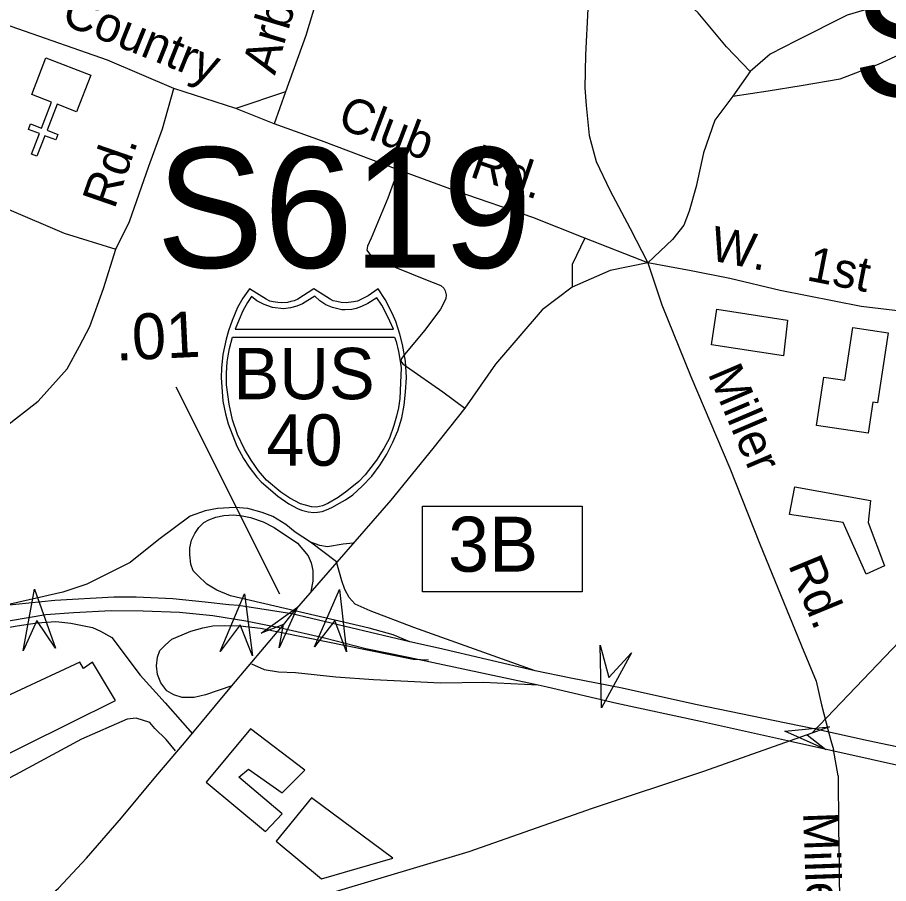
# Model space of a CAD drawing. Extents: x 1547597 to 1699558, y 810033 to 920809.
# Drawn here: x 1621385 to 1623759, y 854822 to 857184 of the extents above; entities that cross this region are included whole.
import ezdxf

# ---------------------------------------------------------------- set-up
doc = ezdxf.new("R2010")
doc.units = 0
for name, color, linetype in [('Exist Cultural Church CELL', 7, 'Continuous'), ('Exist Cultural Shopping Center Building Footprint', 7, 'Continuous'), ('Exist Cultural Warehouse Building Footprint', 7, 'Continuous'), ('Exist Railroad Mainline', 7, 'Continuous'), ('Exist Road Non-System Type 51', 7, 'Continuous'), ('Exist Road Non-System Type 51 Label', 7, 'Continuous'), ('Exist Road Primary Interstate Divided Center Attributed', 7, 'Continuous'), ('Exist Road Primary Interstate Interchange CELL', 7, 'Continuous'), ('Exist Road Primary Interstate Ramp 1 Lane Attributed', 7, 'Continuous'), ('Exist Road Primary Interstate Shield CELL', 7, 'Continuous'), ('Exist Road Primary Interstate Shield Number Label', 7, 'Continuous'), ('Exist Road Primary Interstate Structure Cantilever Sign Attributed CELL', 7, 'Continuous'), ('Exist Road Primary Interstate Structure Ovrhead Sign Attributed CELL', 7, 'Continuous'), ('Exist Road Primary Interstate Structure Ovrhead Sign Number Label', 7, 'Continuous'), ('Exist Road Primary US Mileage Hundredths English Label', 7, 'Continuous'), ('Exist Road Primary US UnDivided 4 Lane Attributed', 7, 'Continuous'), ('Exist Road Secondary Structure Standard Bridge Attributed CELL', 7, 'Continuous')]:
    doc.layers.add(name, color=color, linetype=linetype)

msp = doc.modelspace()

# ---------------------------------------------------------------- linework, layer by layer
at = {"layer": 'Exist Cultural Church CELL'}
msp.add_lwpolyline([(1621545.9, 856926.6), (1621492.8, 856947), (1621465.3, 856876), (1621495.2, 856864.5), (1621489.4, 856849.6), (1621459.6, 856861.1), (1621437.9, 856805), (1621423, 856810.8), (1621444.6, 856866.9), (1621414.8, 856878.4), (1621420.5, 856893.3), (1621450.4, 856881.8), (1621477.8, 856952.8), (1621424.1, 856973.7), (1621462.4, 857073), (1621584.3, 857025.9)], close=True, dxfattribs=at)
at = {"layer": 'Exist Cultural Shopping Center Building Footprint'}
msp.add_lwpolyline([(1620907.7, 854952.7), (1621651.9, 855321.6), (1621589.3, 855426), (1621564.9, 855408.6), (1621554.5, 855426), (1621137.2, 855231.1), (1621144.1, 855206.8), (1620883.3, 855081.5), (1620865.9, 855116.3), (1620834.6, 855098.9)], close=True, dxfattribs=at)
at = {"layer": 'Exist Cultural Warehouse Building Footprint'}
for points in [[(1623291.3, 856387.8), (1623484.1, 856357.9), (1623472.5, 856261.4), (1623276.3, 856291.3)], [(1623562.8, 856071.5), (1623583, 856203), (1623640, 856194.3), (1623662.2, 856338.6), (1623758.4, 856323.8), (1623729.1, 856133.1), (1623716.3, 856135.1), (1623703.2, 856049.9)], [(1623504.1, 855903.6), (1623710.3, 855867), (1623703.6, 855807.1), (1623748.5, 855688.9), (1623698.6, 855665.6), (1623635.4, 855807.1), (1623489.1, 855828.7)], [(1622020.2, 855244.5), (1621899, 855099), (1622060.6, 854964.2), (1622106.4, 855012.7), (1621987.9, 855112.4), (1622014.8, 855134), (1622106.4, 855069.3), (1622168.4, 855131.3)], [(1622213.5, 854835.4), (1622407.5, 854892), (1622186.6, 855056.5), (1622089.6, 854937.8)]]:
    msp.add_lwpolyline(points, close=True, dxfattribs=at)
at = {"layer": 'Exist Railroad Mainline'}
msp.add_lwpolyline([(1620826, 854318.2), (1621032.6, 854389.6), (1621343.6, 854489.6), (1621650.5, 854595.6), (1621961.6, 854699.6), (1622242.6, 854798.1), (1622615.9, 854910.1), (1622951.9, 855027.5), (1623255.9, 855128.9), (1623550.6, 855233.7), (1623868.5, 855565)], dxfattribs=at)
at = {"layer": 'Exist Road Non-System Type 51'}
for p, q in [((1623381.7, 857036.3), (1623334.7, 856969)), ((1621979.5, 856935.1), (1621810.7, 856989.7)), ((1622115.7, 856981.1), (1621979.5, 856935.1)), ((1622115.7, 856981.1), (1622084.7, 856893.3)), ((1622084.7, 856893.3), (1621979.5, 856935.1)), ((1623103.4, 856515), (1622930.9, 856581.8)), ((1623576.2, 855309.2), (1623595.4, 855236.4)), ((1623595.4, 855236.4), (1623601.9, 855212.1)), ((1623601.9, 855212.1), (1623608.7, 855187.8)), ((1623621.7, 855116.1), (1623608.7, 855187.8))]:
    msp.add_line(p, q, dxfattribs=at)
for points in [[(1622239.3, 857361), (1622213.2, 857275.9), (1622171.1, 857134.5), (1622115.7, 856981.1)], [(1622937.3, 857345.3), (1622939.2, 857207.3), (1622933, 857081.4), (1622931.6, 856991.6), (1622934.8, 856943.5), (1622943.3, 856861.5), (1622962.1, 856791.2), (1622999, 856712.7), (1623055.1, 856607.7), (1623103.4, 856515)], [(1623381.7, 857036.3), (1623317, 857103.2), (1623240.5, 857196.4), (1623158, 857271.7), (1623090.5, 857310.7), (1623009.2, 857338), (1622937.3, 857345.3)], [(1621810.7, 856989.7), (1621630, 857066.6), (1621385.8, 857152.6), (1621207, 857215.5), (1621073.8, 857259.6), (1620942.7, 857307.7)], [(1623956.4, 857232.7), (1623854.6, 857232.4), (1623748.4, 857220.1), (1623646, 857189.8), (1623507.1, 857120.2), (1623436.5, 857083.2), (1623381.7, 857036.3)], [(1623334.7, 856969), (1623430.9, 856983.4), (1623521, 856998), (1623627.2, 857016.3), (1623731.7, 857056.4), (1623812.3, 857093.2), (1623892.4, 857103.8), (1623968.3, 857100.6)], [(1621653.2, 856551.7), (1621690.3, 856627.1), (1621742.6, 856778.2), (1621780.1, 856879.7), (1621810.7, 856989.7)], [(1623334.7, 856969), (1623285.8, 856903.7), (1623254.4, 856814.3), (1623234.7, 856722.7), (1623215.7, 856655), (1623201.1, 856617.3), (1623170.5, 856577.9), (1623103.4, 856515)], [(1622422.4, 856768), (1622213.9, 856847.2), (1622084.7, 856893.3)], [(1622422.4, 856768), (1622394.6, 856690.5), (1622348.7, 856581.4), (1622338.7, 856559.6), (1622337.3, 856548.8), (1622346.6, 856535.6), (1622377.9, 856516.9), (1622497.1, 856469.1), (1622538.8, 856452.6), (1622546.7, 856445.5), (1622550.6, 856438.4), (1622553.5, 856427.3), (1622552.3, 856416.3), (1622537.9, 856388.6), (1622495, 856331.3), (1622444.1, 856270.1), (1622431.9, 856253.9), (1622429.8, 856246.3), (1622434.3, 856239.8), (1622445.5, 856232), (1622544.4, 856162.6), (1622603.8, 856118.2)], [(1622930.9, 856581.8), (1622789.9, 856638.1), (1622583.3, 856709.3), (1622422.4, 856768)], [(1621213.9, 856708.3), (1621361, 856660), (1621512, 856595.7), (1621653.2, 856551.7)], [(1622930.9, 856581.8), (1622897.2, 856509.8), (1622897.2, 856448)], [(1620678.7, 855654.7), (1620761, 855691.5), (1620912.2, 855775.2), (1621033.3, 855853.4), (1621154.2, 855927.6), (1621257.2, 856000), (1621350.2, 856066.5), (1621441, 856137.1), (1621520.3, 856226), (1621553.4, 856287.3), (1621582.1, 856341), (1621619.6, 856444.3), (1621653.2, 856551.7)], [(1623103.4, 856515), (1623000, 856493.3), (1622897.2, 856448)], [(1623948.2, 856365.4), (1623860.4, 856374.8), (1623684.9, 856395.6), (1623463.9, 856439.3), (1623326.6, 856471.5), (1623221, 856493), (1623103.4, 856515)], [(1623103.4, 856515), (1623141.5, 856399.6), (1623220.4, 856204.5), (1623326.6, 855955), (1623407.3, 855750), (1623482.9, 855566.3), (1623495.9, 855534.7), (1623522.2, 855470.2), (1623561.5, 855373.9), (1623576.2, 855309.2)], [(1622897.2, 856448), (1622815, 856386.3), (1622687.6, 856238.3), (1622603.8, 856118.2)], [(1622603.8, 856118.2), (1622517.3, 856008.2), (1622402.6, 855867.7), (1622132.4, 855557.4)], [(1621815.5, 855184.2), (1621789.8, 855214.7), (1621759.3, 855245.1), (1621745.3, 855261.5), (1621707.9, 855273.2), (1621683.8, 855270.1), (1621559, 855216), (1621379.8, 855118.6), (1621222.6, 855037.1), (1621106, 854978.9), (1621029.3, 854936)], [(1623621.7, 855116.1), (1623623, 854978.3), (1623624.1, 854864.3), (1623627, 854549.7)]]:
    msp.add_lwpolyline(points, dxfattribs=at)
at = {"layer": 'Exist Road Primary Interstate Divided Center Attributed'}
for points in [[(1622132.4, 855557.4), (1621987.3, 855580.3), (1621960.5, 855582.2), (1621896.7, 855589.9), (1621808.5, 855598.5), (1621707.9, 855603.2), (1621647.1, 855603.2), (1621486.4, 855593.6), (1621344.4, 855579.5)], [(1621094.5, 855465.5), (1621166.7, 855490.4), (1621252.9, 855513.8), (1621365.3, 855539.8), (1621462.3, 855555.5), (1621537.3, 855561.1), (1621639.9, 855567.2), (1621727.6, 855565.8), (1621826, 855561.8), (1621916.9, 855552.9), (1622007.3, 855538.9), (1622102.8, 855519.9)], [(1622796.2, 855402.7), (1622532.6, 855463.7), (1622454.4, 855481), (1622132.4, 855557.4)], [(1622102.8, 855519.9), (1622221.4, 855492.6), (1622334, 855462.8), (1622450.9, 855439.4), (1622804.5, 855363.8)], [(1623560, 855243.5), (1623480.4, 855259.4), (1623233.1, 855310.6), (1623032.6, 855354.7), (1622892.8, 855382), (1622796.2, 855402.7)], [(1622804.5, 855363.8), (1622829, 855358.6), (1623018.1, 855314), (1623246.3, 855265.4), (1623483.3, 855212.3)], [(1624233.7, 855069.8), (1623946.4, 855160.9), (1623703.8, 855211.6), (1623560, 855243.5)], [(1623483.3, 855212.3), (1623830.2, 855134.7), (1623968.5, 855100.4)]]:
    msp.add_lwpolyline(points, dxfattribs=at)
at = {"layer": 'Exist Road Primary Interstate Interchange CELL'}
msp.add_lwpolyline([(1622489.2, 855851), (1622924.1, 855851), (1622924.1, 855617.7), (1622489.2, 855617.7)], close=True, dxfattribs=at)
at = {"layer": 'Exist Road Primary Interstate Ramp 1 Lane Attributed'}
msp.add_line((1622254.6, 855699.5), (1622183.1, 855752.6), dxfattribs=at)
for points in [[(1622183.1, 855752.6), (1622141.3, 855780.4), (1622116, 855800.8), (1622080.4, 855822.8), (1622051.8, 855834.1), (1622012.9, 855844.4), (1621978.3, 855847.3), (1621930.3, 855844.6), (1621896.1, 855838.3), (1621855.7, 855824.3), (1621769.8, 855760.7), (1621691.6, 855697.6), (1621574, 855639), (1621508, 855616.5), (1621344.4, 855579.5)], [(1622454.4, 855481), (1622408.9, 855500.7), (1622343.3, 855518.9), (1621965.6, 855606.8), (1621928.1, 855622.3), (1621900.9, 855638.7), (1621876.6, 855662.6), (1621863.9, 855675.2), (1621856.9, 855693.5), (1621854.6, 855718.8), (1621854.6, 855738), (1621858.8, 855758.6), (1621868.6, 855777.1), (1621879.4, 855792.6), (1621892.5, 855806.7), (1621906.1, 855814.2), (1621925.3, 855821.2), (1621947.3, 855825.9), (1621974.5, 855827.3), (1621997.5, 855824.5), (1622020, 855820.7), (1622054.4, 855808.5), (1622084.4, 855792.8), (1622148.5, 855750), (1622177, 855715.7), (1622185.1, 855697.1), (1622189.9, 855675.8), (1622189.8, 855646.5), (1622184.2, 855618.7)], [(1622299.5, 855750.5), (1622272.3, 855748), (1622229.5, 855740.4), (1622208.5, 855744), (1622183.1, 855752.6)], [(1622796.2, 855402.7), (1622464.9, 855520.2), (1622346.3, 855565.8), (1622305, 855584.4), (1622289.3, 855602.2), (1622277.2, 855623.6), (1622268.7, 855647.9), (1622254.6, 855699.5)], [(1621094.5, 855465.5), (1621118.4, 855461.8), (1621178.4, 855478.2), (1621295.1, 855509.3), (1621384.1, 855524.8), (1621438.4, 855533.2), (1621489.5, 855536.5), (1621529.8, 855531.8), (1621566.8, 855525.3), (1621588.9, 855520.1), (1621610.9, 855510.7), (1621642.3, 855492.9), (1621719.3, 855390.2), (1621787.2, 855315.3), (1621862.1, 855230.4)], [(1621968.9, 855361), (1621897.1, 855336.4), (1621866.7, 855329.4), (1621834, 855329.4), (1621810.6, 855336.4), (1621791.9, 855348.1), (1621775.5, 855369.2), (1621766.1, 855392.6), (1621763.8, 855416), (1621766.1, 855439.4), (1621773.1, 855458.1), (1621787.2, 855472.1), (1621805.9, 855488.5), (1621834, 855500.2), (1621856.9, 855510.5), (1621890.2, 855519.4), (1621917.3, 855524.6), (1621948.6, 855526), (1621991.9, 855524.6), (1622047.6, 855518.5), (1622463.7, 855433.9), (1622505.4, 855432.5)], [(1622022.8, 855421.4), (1622057.1, 855405.8), (1622096, 855399.6), (1622142.7, 855397.3), (1622252.6, 855385.5), (1622355.6, 855378.5), (1622449.2, 855373.8), (1622538.1, 855369.2), (1622655.1, 855371.5), (1622804.5, 855363.8)]]:
    msp.add_lwpolyline(points, dxfattribs=at)
at = {"layer": 'Exist Road Primary Interstate Shield CELL'}
for points in [[(1622192.9, 855833.7), (1622202.4, 855834.6), (1622215.1, 855837.1), (1622227.5, 855841.2), (1622241.6, 855847.4), (1622262.5, 855859), (1622279.2, 855868.8), (1622298.6, 855881.8), (1622324.7, 855905.5), (1622350.7, 855932.9), (1622373.7, 855963.9), (1622392, 855992.9), (1622408, 856026.1), (1622421.5, 856057), (1622432.1, 856092.3), (1622439.2, 856126.6), (1622442.8, 856162.3), (1622445.1, 856201.8), (1622442.5, 856246.4), (1622434.7, 856291.9), (1622427.4, 856320.3), (1622416.4, 856354.2), (1622407.4, 856375.9), (1622386.6, 856414.3), (1622367.8, 856443.9), (1622340.6, 856424.8), (1622322.8, 856415.3), (1622312, 856410.5), (1622300.8, 856408.3), (1622280.3, 856405.8), (1622267.5, 856406.4), (1622255.5, 856409.1), (1622245.4, 856411.3), (1622237.1, 856415.3), (1622192.9, 856443.9), (1622148.6, 856415.3), (1622139.3, 856411.1), (1622129.8, 856409.1), (1622120.7, 856406.6), (1622105.6, 856405.8), (1622094, 856406.2), (1622082.1, 856408.3), (1622072.7, 856410.3), (1622062.2, 856415.3), (1622017.1, 856443.9), (1621999.4, 856418.2), (1621984.9, 856392.8), (1621969.6, 856356.9), (1621960, 856329.1), (1621953.2, 856306.2), (1621944.9, 856264.2), (1621940.5, 856227.7), (1621939.8, 856201.8), (1621944.5, 856137.3), (1621951.6, 856103), (1621958.8, 856075.2), (1621982.7, 856015.1), (1622000.6, 855981.5), (1622016, 855957.4), (1622037.6, 855930.2), (1622049.3, 855917.2), (1622094.1, 855878.1), (1622124, 855857.6), (1622147.9, 855844.7), (1622159.2, 855840.4), (1622176.7, 855835.5)], [(1622022.5, 856423.2), (1622011.5, 856406.3), (1621998.8, 856383.4), (1621988.7, 856359.8), (1621978.3, 856333.6), (1622409.9, 856333.5), (1622399.8, 856355.9), (1622389.1, 856378.4), (1622377.8, 856399), (1622364.1, 856418.9), (1622339.9, 856403.6), (1622322.3, 856395.3), (1622308.1, 856390.4), (1622296.1, 856387.7), (1622277.5, 856386.2), (1622269.2, 856386.7), (1622243.3, 856392.6), (1622225.7, 856399.8), (1622209, 856410.9), (1622195.5, 856423.6), (1622161.3, 856403), (1622146.1, 856396.3), (1622128.7, 856391.8), (1622109.6, 856389.4), (1622080.2, 856392.6), (1622057.1, 856400.6), (1622037.2, 856410.9)], [(1622412.4, 856312.2), (1622417, 856300), (1622423.4, 856272.9), (1622426.7, 856252.1), (1622430.2, 856228.1), (1622429, 856187), (1622427, 856144.4), (1622423.1, 856119.2), (1622417.8, 856096.2), (1622410.7, 856070.8), (1622399.2, 856036.9), (1622383.2, 856008.3), (1622363.4, 855976.5), (1622341.9, 855948.6), (1622332.6, 855937), (1622314.8, 855918.4), (1622282.6, 855892.5), (1622259.1, 855874.9), (1622230.9, 855858.3), (1622216.6, 855851.9), (1622200, 855848.4), (1622186.3, 855849.4), (1622169.6, 855853.8), (1622156.2, 855857.5), (1622126.8, 855873.4), (1622102.9, 855889.3), (1622063.1, 855921.9), (1622041.7, 855947.1), (1622021.6, 855976.4), (1622003.8, 856006.5), (1621984.7, 856046.2), (1621971.2, 856086.1), (1621961.4, 856129.2), (1621954.8, 856181.8), (1621954.1, 856213.9), (1621956.1, 856244.7), (1621959, 856260.9), (1621962.9, 856281), (1621970.8, 856311.9)]]:
    msp.add_lwpolyline(points, close=True, dxfattribs=at)
at = {"layer": 'Exist Road Primary Interstate Structure Cantilever Sign Attributed CELL'}
for points in [[(1621400, 855456.9), (1621430.9, 855624.8), (1621488.1, 855464), (1621437.7, 855539.7)], [(1621937.4, 855454.8), (1622003.6, 855612.2), (1622025, 855442.8), (1621992, 855527.6)], [(1623058.7, 855451.2), (1622977.1, 855301.2), (1622972.7, 855471.9), (1622997.1, 855384.2)]]:
    msp.add_lwpolyline(points, close=True, dxfattribs=at)
at = {"layer": 'Exist Road Primary Interstate Structure Ovrhead Sign Attributed CELL'}
msp.add_lwpolyline([(1622194.5, 855467.3), (1622262.4, 855624), (1622281.9, 855454.4), (1622249.9, 855539.5)], close=True, dxfattribs=at)
at = {"layer": 'Exist Road Primary US Mileage Hundredths English Label'}
msp.add_line((1622099.5, 855610.9), (1621817, 856175.9), dxfattribs=at)
at = {"layer": 'Exist Road Primary US UnDivided 4 Lane Attributed'}
for points in [[(1622132.4, 855557.4), (1622102.8, 855519.9)], [(1621377.2, 854706), (1621496.4, 854809.4), (1621572.6, 854891.2), (1621668.1, 855001.7), (1621761.7, 855114), (1621839.6, 855205.9), (1621968.9, 855361), (1622102.8, 855519.9)]]:
    msp.add_lwpolyline(points, dxfattribs=at)
at = {"layer": 'Exist Road Secondary Structure Standard Bridge Attributed CELL'}
for points in [[(1622049.2, 855504.8), (1622148.1, 855576.1), (1622098.1, 855464.9), (1622109.6, 855528.8)], [(1623588, 855187.7), (1623476.7, 855237.6), (1623598, 855250), (1623536.9, 855227.9)]]:
    msp.add_lwpolyline(points, close=True, dxfattribs=at)

# ---------------------------------------------------------------- texts
at = {"layer": 'Exist Road Non-System Type 51 Label'}
for s, rotation, p in [('Arbor', 73.4266, (1622086.4, 857024.2)), ('Country', 338.0803, (1621500.3, 857167.5)), ('Club', 339.1836, (1622253.1, 856885)), ('Rd.', 70.9022, (1621649.1, 856658.5)), ('Rd.', 340.9828, (1622614.4, 856750.6)), ('W.', 348.8144, (1623268.4, 856522.5)), ('1st', 348.8144, (1623532.7, 856467.5)), ('Miller', 293.0573, (1623265.4, 856213.3)), ('Rd.', 292.3845, (1623484.6, 855691.5)), ('Miller', 272.0938, (1623526, 855016))]:
    msp.add_text(s, height=95, rotation=rotation, dxfattribs=at).set_placement(p)
at = {"layer": 'Exist Road Primary Interstate Interchange CELL'}
msp.add_text('3B', height=150, dxfattribs=at).set_placement((1622558.7, 855672.6))
at = {"layer": 'Exist Road Primary Interstate Shield Number Label'}
for s, p in [('BUS', (1621973.5, 856142.7)), ('40', (1622062.9, 855961.4))]:
    msp.add_text(s, height=140, dxfattribs=at).set_placement(p)
at = {"layer": 'Exist Road Primary Interstate Structure Ovrhead Sign Number Label'}
for s, p in [('S616', (1623660.9, 856967.4)), ('S619', (1621763, 856501.1))]:
    msp.add_text(s, height=328.08, dxfattribs=at).set_placement(p)
at = {"layer": 'Exist Road Primary US Mileage Hundredths English Label'}
msp.add_text('.01', height=125, rotation=2.7889, dxfattribs=at).set_placement((1621653.4, 856247.5))

doc.saveas('drawing.dxf')
